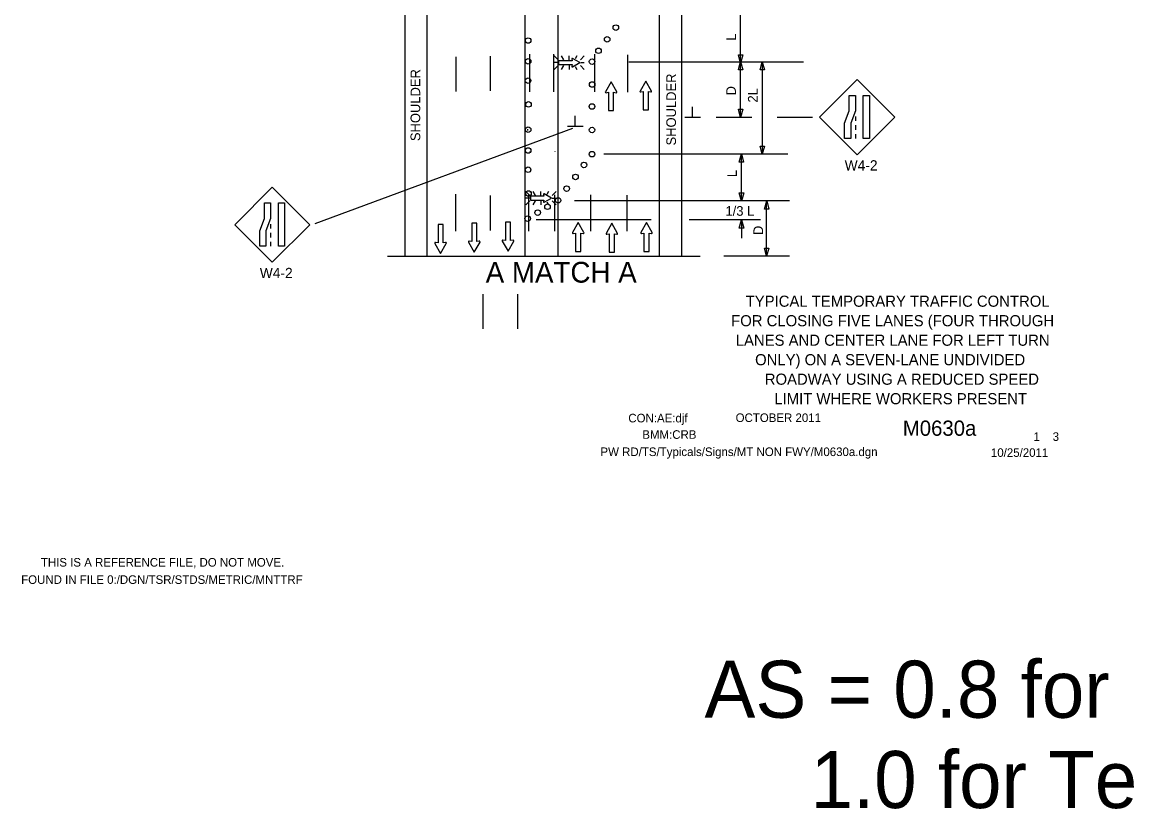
# Model space of a CAD drawing. Extents: x 20837 to 23689, y 414 to 2167.
# Drawn here: x 20837 to 21636, y 414 to 983 of the extents above; entities that cross this region are included whole.
import ezdxf

# ---------------------------------------------------------------- set-up
doc = ezdxf.new("R2010")
doc.units = 0
for name, color, linetype in [('ALI_LEGAL_EX', 7, 'Continuous'), ('BORDER_SIGNAL_WO', 7, 'Continuous'), ('MT_SCRATCH_LEVEL_E', 7, 'Continuous'), ('PAVT_EDGE_EX', 7, 'Continuous'), ('SCRATCH_LEVEL_A', 7, 'Continuous'), ('TRAFFIC_SIGNS_PR', 7, 'Continuous'), ('TYPICAL_EX', 7, 'Continuous'), ('TYPICAL_TEXT_DIMEN_PR', 7, 'Continuous')]:
    doc.layers.add(name, color=color, linetype=linetype)

msp = doc.modelspace()

# ---------------------------------------------------------------- linework, layer by layer
at = {"layer": 'ALI_LEGAL_EX'}
for points in [[(21203.7, 932.21), (21203.7, 959.46)], [(21221.14, 932.21), (21221.14, 959.46)], [(21250.8, 932.21), (21250.8, 959.46)], [(21274.54, 932.1), (21274.54, 959.05)], [(21150.59, 932.38), (21150.59, 957.49)], [(21175.31, 932.9), (21175.31, 958.01)], [(21202.04, 904.95), (21202.04, 904.39)], [(21202.28, 904.95), (21202.28, 905.15)], [(21204.09, 888.98), (21204.09, 889.18)], [(21221.99, 888.98), (21221.99, 889.18)], [(21248.09, 888.98), (21248.09, 889.18)], [(21150.18, 831.5), (21150.18, 858.38)], [(21175.44, 832.12), (21175.44, 857.35)], [(21203.11, 831.45), (21203.11, 857.76)], [(21204.18, 859.41), (21204.18, 859.61)], [(21221.78, 831.45), (21221.78, 857.76)], [(21247.88, 831.45), (21247.88, 857.76)], [(21274.24, 831.47), (21274.24, 857.55)]]:
    msp.add_lwpolyline(points, dxfattribs=at)
at = {"layer": 'MT_SCRATCH_LEVEL_E'}
for p, q in [((21262.5, 939.56), (21258.39, 932.32)), ((21262.5, 939.56), (21258.39, 932.32)), ((21266.65, 932.32), (21262.5, 939.56)), ((21266.65, 932.32), (21262.5, 939.56)), ((21287.59, 940.07), (21283.48, 932.83)), ((21287.59, 940.07), (21283.48, 932.83)), ((21291.74, 932.83), (21287.59, 940.07)), ((21291.74, 932.83), (21287.59, 940.07)), ((21258.87, 931.64), (21260.65, 931.95)), ((21258.87, 931.64), (21260.65, 931.95)), ((21260.65, 931.95), (21260.65, 918.7)), ((21260.65, 931.95), (21260.65, 918.7)), ((21264.39, 918.7), (21264.39, 931.95)), ((21264.39, 931.95), (21266.17, 931.64)), ((21264.39, 918.7), (21264.39, 931.95)), ((21264.39, 931.95), (21266.17, 931.64)), ((21283.96, 932.15), (21285.74, 932.46)), ((21283.96, 932.15), (21285.74, 932.46)), ((21285.74, 932.46), (21285.74, 919.21)), ((21285.74, 932.46), (21285.74, 919.21)), ((21289.48, 919.21), (21289.48, 932.46)), ((21289.48, 932.46), (21291.26, 932.15)), ((21289.48, 919.21), (21289.48, 932.46)), ((21289.48, 932.46), (21291.26, 932.15)), ((21285.74, 919.21), (21289.48, 919.21)), ((21285.74, 919.21), (21289.48, 919.21)), ((21260.65, 918.7), (21264.39, 918.7)), ((21260.65, 918.7), (21264.39, 918.7)), ((21141.12, 836.36), (21137.37, 836.36)), ((21137.37, 836.36), (21137.37, 823.1)), ((21141.12, 836.36), (21137.37, 836.36)), ((21137.37, 836.36), (21137.37, 823.1)), ((21141.12, 823.1), (21141.12, 836.36)), ((21141.12, 823.1), (21141.12, 836.36)), ((21165.48, 837.28), (21161.74, 837.28)), ((21161.74, 837.28), (21161.74, 824.02)), ((21165.48, 837.28), (21161.74, 837.28)), ((21161.74, 837.28), (21161.74, 824.02)), ((21165.48, 824.02), (21165.48, 837.28)), ((21165.48, 824.02), (21165.48, 837.28)), ((21189.84, 837.95), (21186.1, 837.95)), ((21186.1, 837.95), (21186.1, 824.69)), ((21189.84, 837.95), (21186.1, 837.95)), ((21186.1, 837.95), (21186.1, 824.69)), ((21189.84, 824.69), (21189.84, 837.95)), ((21189.84, 824.69), (21189.84, 837.95)), ((21238.75, 837.71), (21234.64, 830.47)), ((21238.75, 837.71), (21234.64, 830.47)), ((21242.9, 830.47), (21238.75, 837.71)), ((21242.9, 830.47), (21238.75, 837.71)), ((21263.02, 837.2), (21258.91, 829.96)), ((21263.02, 837.2), (21258.91, 829.96)), ((21267.17, 829.96), (21263.02, 837.2)), ((21267.17, 829.96), (21263.02, 837.2)), ((21288.11, 837.71), (21284, 830.47)), ((21288.11, 837.71), (21284, 830.47)), ((21292.26, 830.47), (21288.11, 837.71)), ((21292.26, 830.47), (21288.11, 837.71)), ((21137.37, 823.1), (21135.6, 823.41)), ((21137.37, 823.1), (21135.6, 823.41)), ((21142.89, 823.41), (21141.12, 823.1)), ((21142.89, 823.41), (21141.12, 823.1)), ((21159.48, 823.66), (21163.63, 816.41)), ((21159.48, 823.66), (21163.63, 816.41)), ((21161.74, 824.02), (21159.96, 824.34)), ((21161.74, 824.02), (21159.96, 824.34)), ((21163.63, 816.41), (21167.74, 823.66)), ((21163.63, 816.41), (21167.74, 823.66)), ((21167.26, 824.34), (21165.48, 824.02)), ((21167.26, 824.34), (21165.48, 824.02)), ((21183.84, 824.33), (21187.99, 817.08)), ((21183.84, 824.33), (21187.99, 817.08)), ((21186.1, 824.69), (21184.32, 825.01)), ((21186.1, 824.69), (21184.32, 825.01)), ((21187.99, 817.08), (21192.1, 824.33)), ((21187.99, 817.08), (21192.1, 824.33)), ((21191.62, 825.01), (21189.84, 824.69)), ((21191.62, 825.01), (21189.84, 824.69)), ((21235.12, 829.79), (21236.9, 830.1)), ((21235.12, 829.79), (21236.9, 830.1)), ((21236.9, 830.1), (21236.9, 816.85)), ((21236.9, 830.1), (21236.9, 816.85)), ((21240.64, 816.85), (21240.64, 830.1)), ((21240.64, 830.1), (21242.42, 829.79)), ((21240.64, 816.85), (21240.64, 830.1)), ((21240.64, 830.1), (21242.42, 829.79)), ((21259.39, 829.28), (21261.17, 829.59)), ((21259.39, 829.28), (21261.17, 829.59)), ((21261.17, 829.59), (21261.17, 816.33)), ((21261.17, 829.59), (21261.17, 816.33)), ((21264.91, 816.33), (21264.91, 829.59)), ((21264.91, 829.59), (21266.69, 829.28)), ((21264.91, 816.33), (21264.91, 829.59)), ((21264.91, 829.59), (21266.69, 829.28)), ((21284.48, 829.79), (21286.26, 830.1)), ((21284.48, 829.79), (21286.26, 830.1)), ((21286.26, 830.1), (21286.26, 816.85)), ((21286.26, 830.1), (21286.26, 816.85)), ((21290, 816.85), (21290, 830.1)), ((21290, 830.1), (21291.78, 829.79)), ((21290, 816.85), (21290, 830.1)), ((21290, 830.1), (21291.78, 829.79)), ((21135.12, 822.73), (21139.26, 815.49)), ((21135.12, 822.73), (21139.26, 815.49)), ((21139.26, 815.49), (21143.38, 822.73)), ((21139.26, 815.49), (21143.38, 822.73)), ((21236.9, 816.85), (21240.64, 816.85)), ((21236.9, 816.85), (21240.64, 816.85)), ((21261.17, 816.33), (21264.91, 816.33)), ((21261.17, 816.33), (21264.91, 816.33)), ((21286.26, 816.85), (21290, 816.85)), ((21286.26, 816.85), (21290, 816.85))]:
    msp.add_line(p, q, dxfattribs=at)
for centre, start, end in [((21258.8, 932.1), 150.42484, 279.96381), ((21258.8, 932.1), 150.42484, 279.96381), ((21266.24, 932.1), 260.03619, 29.77312), ((21266.24, 932.1), 260.03619, 29.77312), ((21283.89, 932.61), 150.42484, 279.96381), ((21283.89, 932.61), 150.42484, 279.96381), ((21291.33, 932.61), 260.03619, 29.77312), ((21291.33, 932.61), 260.03619, 29.77312), ((21135.53, 822.95), 80.03619, 209.77312), ((21135.53, 822.95), 80.03619, 209.77312), ((21142.97, 822.96), 330.42484, 99.96381), ((21142.97, 822.96), 330.42484, 99.96381), ((21159.89, 823.88), 80.03619, 209.77312), ((21159.89, 823.88), 80.03619, 209.77312), ((21167.33, 823.88), 330.42484, 99.96381), ((21167.33, 823.88), 330.42484, 99.96381), ((21184.25, 824.55), 80.03619, 209.77312), ((21184.25, 824.55), 80.03619, 209.77312), ((21191.69, 824.55), 330.42484, 99.96381), ((21191.69, 824.55), 330.42484, 99.96381), ((21235.05, 830.25), 150.42484, 279.96381), ((21235.05, 830.25), 150.42484, 279.96381), ((21242.49, 830.25), 260.03619, 29.77312), ((21242.49, 830.25), 260.03619, 29.77312), ((21259.32, 829.73), 150.42484, 279.96381), ((21259.32, 829.73), 150.42484, 279.96381), ((21266.76, 829.74), 260.03619, 29.77312), ((21266.76, 829.74), 260.03619, 29.77312), ((21284.41, 830.25), 150.42484, 279.96381), ((21284.41, 830.25), 150.42484, 279.96381), ((21291.85, 830.25), 260.03619, 29.77312), ((21291.85, 830.25), 260.03619, 29.77312)]:
    msp.add_arc(centre, 0.463, start, end, dxfattribs=at)
at = {"layer": 'PAVT_EDGE_EX'}
for p, q in [((21129.4, 1637.35), (21129.4, 813.35)), ((21297.4, 1637.35), (21297.4, 813.35)), ((21313.4, 1636.75), (21313.4, 813.35)), ((21200.14, 1162.94), (21200.14, 813.35)), ((21224.14, 1153.96), (21224.14, 813.35))]:
    msp.add_line(p, q, dxfattribs=at)
for points in [[(21170.09, 760.99), (21170.09, 785.99)], [(21170.09, 760.99), (21170.09, 785.99)], [(21195.09, 760.99), (21195.09, 785.99)], [(21195.09, 760.99), (21195.09, 785.99)]]:
    msp.add_lwpolyline(points, dxfattribs=at)
at = {"layer": 'TRAFFIC_SIGNS_PR'}
for p, q in [((21224.17, 955.36), (21221.35, 958.18)), ((21224.17, 953.33), (21221.35, 953.33)), ((21224.17, 951.3), (21221.35, 948.48)), ((21226.47, 958.18), (21228.1, 955.36)), ((21228.12, 951.3), (21226.5, 948.48)), ((21232.26, 955.36), (21232.26, 958.18)), ((21232.26, 951.3), (21232.26, 948.48)), ((21237.73, 958.18), (21236.52, 956.09)), ((21243.16, 958.18), (21240.35, 955.36)), ((21240.35, 953.33), (21243.16, 953.33)), ((21243.16, 948.48), (21240.35, 951.3)), ((21236.44, 950.66), (21237.7, 948.48)), ((21440.52, 941.11), (21413.36, 913.96)), ((21467.67, 913.96), (21440.52, 941.11)), ((21413.36, 913.96), (21440.52, 886.81)), ((21439.27, 914.45), (21439.27, 911.25)), ((21440.52, 886.81), (21467.67, 913.96)), ((21439.27, 908.05), (21439.27, 904.85)), ((21439.27, 901.65), (21439.27, 898.45)), ((21017.52, 863.31), (20990.37, 836.16)), ((21044.68, 836.16), (21017.52, 863.31)), ((21203.74, 857.41), (21200.92, 860.23)), ((21203.74, 855.38), (21200.92, 855.38)), ((21206.04, 860.23), (21207.67, 857.41)), ((21211.83, 857.41), (21211.83, 860.23)), ((21217.3, 860.23), (21216.09, 858.14)), ((21222.73, 860.23), (21219.91, 857.41)), ((21219.91, 855.38), (21222.73, 855.38)), ((21203.74, 853.35), (21200.92, 850.53)), ((21207.69, 853.35), (21206.06, 850.53)), ((21211.83, 853.35), (21211.83, 850.53)), ((21216.01, 852.71), (21217.27, 850.53)), ((21222.73, 850.53), (21219.91, 853.35)), ((20990.37, 836.16), (21017.52, 809.01)), ((21016.28, 836.65), (21016.28, 833.45)), ((21017.52, 809.01), (21044.68, 836.16)), ((21016.28, 830.25), (21016.28, 827.05)), ((21016.28, 823.85), (21016.28, 820.65))]:
    msp.add_line(p, q, dxfattribs=at)
for points in [[(21234.09, 956.01), (21234.32, 954.72), (21224.59, 954.72), (21224.59, 951.97), (21234.32, 951.97), (21234.08, 950.67)], [(21234.59, 950.31), (21239.9, 953.33), (21234.59, 956.37)], [(21213.65, 858.06), (21213.88, 856.77), (21204.16, 856.77), (21204.16, 854.02), (21213.88, 854.02), (21213.65, 852.72)], [(21214.15, 852.37), (21219.46, 855.38), (21214.15, 858.42)]]:
    msp.add_lwpolyline(points, dxfattribs=at)
for points in [[(21439.27, 929.7), (21439.27, 918.52), (21435.92, 909.63), (21435.92, 898.45), (21431.43, 898.45), (21431.43, 909.63), (21434.78, 918.52), (21434.78, 929.7)], [(21449.4, 929.7), (21449.4, 898.45), (21444.91, 898.45), (21444.91, 929.7)], [(21016.28, 851.9), (21016.28, 840.72), (21012.93, 831.83), (21012.93, 820.65), (21008.44, 820.65), (21008.44, 831.83), (21011.78, 840.72), (21011.78, 851.9)], [(21026.41, 851.9), (21026.41, 820.65), (21021.92, 820.65), (21021.92, 851.9)]]:
    msp.add_lwpolyline(points, close=True, dxfattribs=at)
for centre in [(21265.98, 978.68), (21202.56, 969.31), (21259.72, 970.19), (21253.44, 961.92), (21202.56, 954.28), (21248.76, 954.08), (21202.51, 940.33), (21248.85, 937.54), (21202.83, 923.15), (21248.69, 921.65), (21202.56, 904.89), (21248.74, 904.68), (21202.56, 889.86), (21248.73, 887.22), (21242.94, 879.41), (21202.51, 875.92), (21236.78, 870.74), (21230.4, 862.28), (21202.83, 858.73), (21224.22, 853.8), (21209.47, 844.95), (21216.58, 849.19), (21202.24, 840.6)]:
    msp.add_circle(centre, 2, dxfattribs=at)
for centre, start, end in [((21234.42, 956.07), 61.48329, 189.95933), ((21234.42, 950.61), 170.73078, 298.89165), ((21213.99, 858.12), 61.48329, 189.95933), ((21213.99, 852.67), 170.73078, 298.89165)]:
    msp.add_arc(centre, 0.341, start, end, dxfattribs=at)
at = {"layer": 'TYPICAL_EX'}
msp.add_line((21113.4, 1637.05), (21113.4, 813.35), dxfattribs=at)
at = {"layer": 'TYPICAL_TEXT_DIMEN_PR'}
for p, q in [((21356.14, 953.77), (21356.14, 988.38)), ((21356.14, 953.05), (21354.57, 958.91)), ((21354.57, 958.91), (21356.14, 958.91)), ((21356.14, 958.91), (21357.71, 958.91)), ((21357.71, 958.91), (21356.14, 953.05)), ((21401.6, 953.77), (21275.45, 953.77)), ((21354.57, 948.2), (21356.14, 954.06)), ((21356.14, 954.06), (21357.71, 948.2)), ((21356.14, 913.77), (21356.14, 953.77)), ((21370.25, 948.17), (21371.82, 954.03)), ((21371.75, 953.5), (21371.75, 887.32)), ((21371.82, 954.03), (21373.39, 948.17)), ((21356.14, 948.2), (21354.57, 948.2)), ((21357.71, 948.2), (21356.14, 948.2)), ((21371.82, 948.17), (21370.25, 948.17)), ((21373.39, 948.17), (21371.82, 948.17)), ((21321.45, 913.73), (21321.45, 921.52)), ((21356.14, 913.77), (21354.57, 919.63)), ((21354.57, 919.63), (21356.14, 919.63)), ((21356.14, 919.63), (21357.71, 919.63)), ((21357.71, 919.63), (21356.14, 913.77)), ((21236.64, 907.22), (21236.64, 915)), ((21327.08, 913.73), (21315.83, 913.73)), ((21364.33, 913.77), (21338.49, 913.77)), ((21408.2, 913.77), (21382.62, 913.77)), ((21234.7, 905.65), (21048.37, 836.92)), ((21242.27, 907.22), (21231.02, 907.22)), ((21390.41, 887.25), (21257.22, 887.25)), ((21355.23, 881.49), (21356.8, 887.35)), ((21356.72, 886.94), (21356.72, 853.55)), ((21356.8, 887.35), (21358.37, 881.49)), ((21371.83, 887.13), (21370.26, 892.99)), ((21370.26, 892.99), (21371.83, 892.99)), ((21371.83, 892.99), (21373.4, 892.99)), ((21373.4, 892.99), (21371.83, 887.13)), ((21356.8, 881.49), (21355.23, 881.49)), ((21358.37, 881.49), (21356.8, 881.49)), ((21356.85, 853.32), (21355.28, 859.18)), ((21355.28, 859.18), (21356.85, 859.18)), ((21356.85, 859.18), (21358.42, 859.18)), ((21358.42, 859.18), (21356.85, 853.32)), ((21391.49, 853.35), (21236.08, 853.35)), ((21373.51, 847.49), (21375.08, 853.35)), ((21375.08, 847.49), (21373.51, 847.49)), ((21375.01, 813.35), (21375.01, 852.91)), ((21375.08, 853.35), (21376.65, 847.49)), ((21376.65, 847.49), (21375.08, 847.49)), ((21291.52, 839.6), (21208.33, 839.6)), ((21370.6, 839.6), (21319.04, 839.6)), ((21355.28, 833.74), (21356.85, 839.6)), ((21356.78, 839.45), (21356.78, 826.46)), ((21356.85, 839.6), (21358.42, 833.74)), ((21356.85, 833.74), (21355.28, 833.74)), ((21358.42, 833.74), (21356.85, 833.74)), ((21375.01, 813.35), (21373.44, 819.21)), ((21373.44, 819.21), (21375.01, 819.21)), ((21375.01, 819.21), (21376.58, 819.21)), ((21376.58, 819.21), (21375.01, 813.35)), ((21100.93, 813.35), (21326.94, 813.35)), ((21391.49, 813.35), (21344.16, 813.35))]:
    msp.add_line(p, q, dxfattribs=at)

# ---------------------------------------------------------------- texts
at = {"layer": 'BORDER_SIGNAL_WO'}
for s, height, p in [('TYPICAL TEMPORARY TRAFFIC CONTROL', 8.0393, (21359.86, 776.88)), ('FOR CLOSING FIVE LANES (FOUR THROUGH', 8.0393, (21349.36, 762.78)), ('LANES AND CENTER LANE FOR LEFT TURN', 8.0393, (21352.7, 748.69)), ('ONLY) ON A SEVEN-LANE UNDIVIDED', 8.0393, (21366.67, 734.6)), ('ROADWAY USING A REDUCED SPEED', 8.0393, (21373.67, 720.51)), ('LIMIT WHERE WORKERS PRESENT', 8.0393, (21380.57, 706.42)), ('CON:AE:djf', 6.2, (21275, 693.3)), ('    OCTOBER 2011    ', 6.2, (21343.39, 693.58)), ('BMM:CRB   ', 6.2, (21285.12, 681.42)), ('    M0630a   ', 11, (21457.17, 683.62)), (' 1    3 ', 6.2, (21565.76, 679.94)), ('PW RD/TS/Typicals/Signs/MT NON FWY/M0630a.dgn    ', 6.2, (21254.86, 668.96)), ('10/25/2011    ', 6.2, (21537.24, 668.38)), ('AS = 0.8 for Sign Cells', 41.2877, (21330.07, 479.79)), ('     1.0 for Text Cells', 41.2877, (21330.07, 414.51))]:
    msp.add_text(s, height=height, dxfattribs=at).set_placement(p)
at = {"layer": 'SCRATCH_LEVEL_A'}
for s, p in [('THIS IS A REFERENCE FILE, DO NOT MOVE.', (20850.17, 589.06)), ('FOUND IN FILE 0:/DGN/TSR/STDS/METRIC/MNTTRF', (20835.9, 576.56))]:
    msp.add_text(s, height=6.2, dxfattribs=at).set_placement(p)
at = {"layer": 'TRAFFIC_SIGNS_PR'}
for p in [(21431.47, 875.37), (21008.48, 797.57)]:
    msp.add_text('W4-2', height=7.44, dxfattribs=at).set_placement(p)
at = {"layer": 'TYPICAL_TEXT_DIMEN_PR'}
for s, p in [('L', (21352.92, 969.27)), ('SHOULDER', (21124.5, 896.63)), ('SHOULDER', (21309.48, 893.46)), ('D', (21352.82, 929.66)), ('2L', (21368.52, 924.51)), ('L', (21353.52, 870.57)), ('D', (21372.45, 828.7))]:
    msp.add_text(s, height=7, rotation=90, dxfattribs=at).set_placement(p)
for s, height, p in [('1/3 L', 7, (21345.28, 842.65)), ('A MATCH A', 15, (21171.85, 794.33))]:
    msp.add_text(s, height=height, dxfattribs=at).set_placement(p)

doc.saveas('drawing.dxf')
